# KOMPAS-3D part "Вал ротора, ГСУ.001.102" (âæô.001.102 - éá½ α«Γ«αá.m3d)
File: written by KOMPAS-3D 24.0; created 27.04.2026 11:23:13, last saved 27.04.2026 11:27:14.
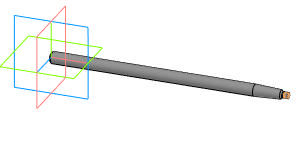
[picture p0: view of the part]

Document properties: Автор: User7; Полное имя файла: C:\Users\User7\Desktop\Двигатель мясорубки\ГСУ.001.102 - Вал ротора.m3d

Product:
- Part/product: Вал ротора  | designation ГСУ.001.102
    Масса: 0.060496

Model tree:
1. Эскиз:1
2. Элемент выдавливания:1
     Расстояние 1 = 138
3. Эскиз:2  (with: Грань.Элемент выдавливания:1, Ребро.Элемент выдавливания:1)
4. Элемент выдавливания:2
     Расстояние 1 = 18; Угол 1 = 3
5. Эскиз:3  (with: Грань.Элемент выдавливания:2, Ребро.Элемент выдавливания:2)
6. Элемент выдавливания:4
     Расстояние 1 = 2
7. Скругление:1  (with: Ребро.Элемент выдавливания:4)
     Радиус = 1
8. Эскиз:4  (with: Грань.Элемент выдавливания:4)
9. Элемент выдавливания:5  (with: Грань.Элемент выдавливания:1)
     Расстояние 1 = 3; Смещение 1 = 161
10. Скругление:2  (with: Ребро.Элемент выдавливания:4)
     Радиус = 0.5
11. Условное изображение резьбы:2  (with: Грань.Элемент выдавливания:5, Ребро.Элемент выдавливания:5, Ребро.Скругление:2)  (labels: M4; cil0_24705-2004 coarse)
     Длина резьбы = 3; Шаг резьбы = 0.7; Номинальный диаметр резьбы = 4
12. Подгонка:2  (with: Грань.Скругление:2, Грань.Элемент выдавливания:5)
13. Фаска:1  (with: Ребро.Элемент выдавливания:1)
     Угол = 45; Длина 1 = 1; Длина 2 = 1

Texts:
  ГСУ.001.102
